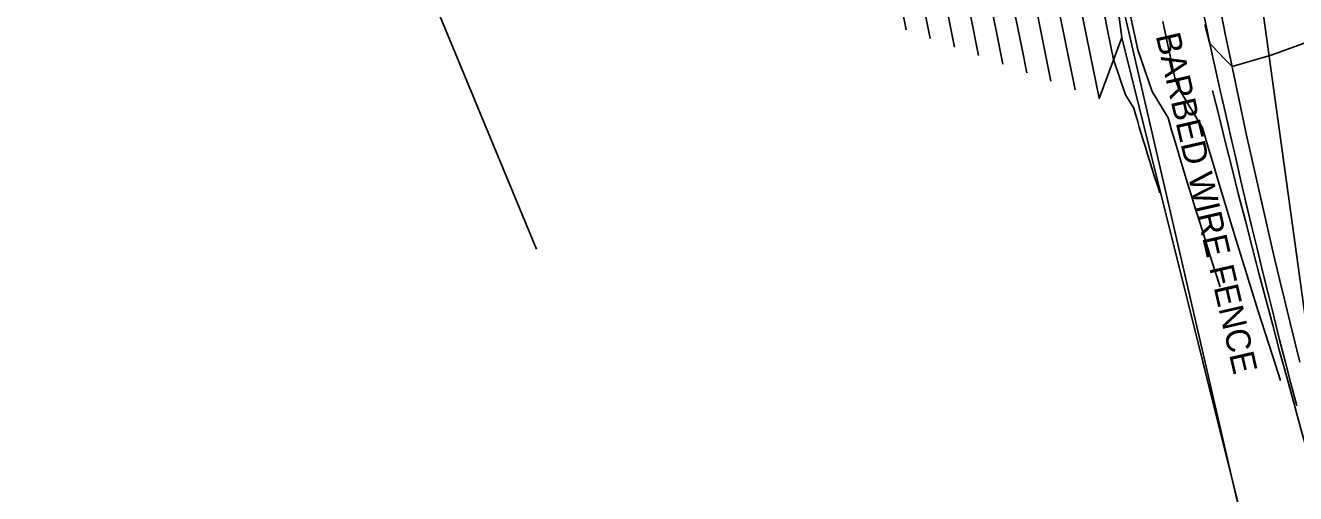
# Model space of a CAD drawing. Extents: x 487096 to 489566, y 221939 to 224454.
# Drawn here: x 488250.6 to 488416.7, y 222799.6 to 222860.8 of the extents above; entities that cross this region are included whole.
import ezdxf

# ---------------------------------------------------------------- set-up
doc = ezdxf.new("R2010")
doc.units = 0
for name, color, linetype in [('SV_FENC_FENCES', 7, 'Continuous'), ('SV_FENC_FENCES_TX', 7, 'Continuous'), ('SV_GDRL_GR', 7, 'Continuous'), ('SV_ROAD_BITRD', 7, 'Continuous'), ('SV_ROWL_HWYLOC', 7, 'Continuous'), ('SV_SURF_INDEX_CONTOUR', 7, 'Continuous'), ('SV_SURF_INTER_CONTOUR', 7, 'Continuous'), ('SV_TRAF_PVMTL', 7, 'Continuous'), ('SV_TREE_TREEVEG', 7, 'Continuous'), ('SV_UTOH_OVERHEAD_LINES', 7, 'Continuous'), ('SV_WATR_INWETF', 7, 'Continuous')]:
    doc.layers.add(name, color=color, linetype=linetype)

msp = doc.modelspace()

# ---------------------------------------------------------------- linework, layer by layer
at = {"layer": 'SV_FENC_FENCES'}
msp.add_lwpolyline([(488391.05, 222851.3), (488394, 222859.24), (488391.81, 222875.89)], dxfattribs=at)
at = {"layer": 'SV_GDRL_GR'}
msp.add_lwpolyline([(488405.88, 222852.34), (488406.72, 222848.92), (488407.57, 222845.5), (488408.43, 222842.09), (488409.29, 222838.67), (488410.17, 222835.26), (488411.05, 222831.85), (488411.94, 222828.45), (488412.83, 222825.04), (488413.74, 222821.64), (488414.65, 222818.24), (488415.57, 222814.84), (488416.5, 222811.45), (488417.43, 222808.05), (488418.37, 222804.66), (488419.33, 222801.27), (488420.28, 222797.88)], dxfattribs=at)
at = {"layer": 'SV_ROAD_BITRD'}
msp.add_lwpolyline([(488403.06, 222870.14), (488403.68, 222867.17), (488404.3, 222864.2), (488404.94, 222861.24), (488405.58, 222858.27), (488406.23, 222855.31), (488406.88, 222852.34), (488407.55, 222849.38), (488408.22, 222846.42), (488408.9, 222843.47), (488409.59, 222840.51), (488410.28, 222837.56), (488410.98, 222834.61), (488411.69, 222831.66), (488412.41, 222828.71), (488413.14, 222825.76), (488413.87, 222822.82), (488414.61, 222819.88), (488415.36, 222816.93), (488416.12, 222814), (488416.89, 222811.06)], dxfattribs=at)
at = {"layer": 'SV_ROWL_HWYLOC'}
msp.add_lwpolyline([(488415.39, 223241.14), (488415.01, 223209.78), (488407.48, 223152.68), (488402.8, 223123.48), (488396.48, 223078.48), (488389.41, 223042.33), (488386.96, 223020.94), (488384.51, 222999.56), (488386.77, 222964.1), (488387.65, 222918.23), (488391.82, 222875.91), (488394, 222859.24), (488415.21, 222774.39)], dxfattribs=at)
at = {"layer": 'SV_SURF_INDEX_CONTOUR'}
for points in [[(488361.03, 222885.62), (488362.59, 222876.48), (488363.45, 222872.07), (488364.06, 222869.06), (488365.81, 222860.25)], [(488376.78, 222879.28), (488377.31, 222876.19), (488379.42, 222865.36), (488380.93, 222857.95), (488381.59, 222854.65)], [(488406.87, 222826.66), (488406.19, 222828.78), (488405.53, 222830.83), (488404.9, 222832.83), (488404.28, 222834.78), (488403.69, 222836.68), (488403.12, 222838.53), (488402.56, 222840.34), (488402.03, 222842.1), (488401.51, 222843.82), (488401.01, 222845.5), (488400.52, 222847.14), (488400.05, 222848.74), (488397.96, 222852.18), (488396.11, 222857.64), (488395.64, 222859.89), (488393.92, 222867.71)]]:
    msp.add_lwpolyline(points, dxfattribs=at)
at = {"layer": 'SV_SURF_INTER_CONTOUR'}
for points in [[(488330.36, 223253.85), (488333.72, 223206.86), (488336.41, 223199.13), (488339.34, 223176.14), (488341.3, 223168.89), (488341.3, 223168.78), (488341.3, 223168.7), (488341.25, 223167.91), (488342.11, 223162.38), (488351.69, 223120.88), (488344.09, 223092.29), (488344.07, 223086.72), (488348.88, 223046.65), (488349.88, 223039.17), (488349.71, 223006.96), (488350.12, 222991.02), (488358.36, 222946.07), (488360.64, 222921.92), (488363.3, 222889.49), (488365.53, 222876.42), (488366.64, 222870.73), (488367.44, 222866.83), (488368.96, 222859.13)], [(488372.12, 222858.01), (488370.81, 222864.61), (488369.84, 222869.39), (488368.47, 222876.36), (488365.75, 222892.37), (488363.35, 222921.55), (488360.89, 222947.67), (488353.37, 222988.63), (488352.92, 223006.27), (488353.11, 223041.95), (488352.7, 223045.03), (488348.94, 223076.26), (488347.53, 223089.21), (488348.29, 223091.81), (488355.92, 223120.53), (488348.77, 223151.52), (488346.42, 223166.72), (488346.54, 223168.9), (488346.55, 223169.1), (488346.56, 223169.4), (488341.16, 223189.35), (488339.56, 223201.89), (488338.09, 223206.12), (488336.26, 223231.76)], [(488384.74, 222853.53), (488384.31, 222855.73), (488382.62, 222864.02), (488380.25, 222876.13), (488375.52, 222903.91), (488374.19, 222920.07), (488370.98, 222954.08), (488366.4, 222979.07), (488365.77, 223003.54)], [(488368.99, 223002.86), (488369.65, 222976.67), (488373.5, 222955.68), (488376.9, 222919.7), (488377.96, 222906.79), (488383.2, 222876.07), (488385.81, 222862.68), (488387.68, 222853.51), (488387.9, 222852.41)], [(488372.2, 223002.18), (488372.91, 222974.28), (488376.03, 222957.28), (488379.61, 222919.33), (488380.4, 222909.68), (488386.14, 222876.01), (488389.01, 222861.34), (488391.05, 222851.32), (488391.06, 222851.3), (488391.06, 222851.29), (488391.07, 222851.27), (488391.07, 222851.26)], [(488375.41, 223001.5), (488376.16, 222971.89), (488378.55, 222958.88), (488382.32, 222918.96), (488382.84, 222912.56), (488389.09, 222875.95), (488392.2, 222859.99), (488392.94, 222856.38), (488394.51, 222851.74), (488395.56, 222850.02), (488395.79, 222849.22), (488396.04, 222848.4), (488396.29, 222847.55), (488396.55, 222846.69), (488396.82, 222845.81), (488397.09, 222844.91), (488397.38, 222843.98), (488397.68, 222843.03), (488397.98, 222842.05), (488398.3, 222841.05), (488398.63, 222840.02), (488398.97, 222838.96)], [(488375.28, 222856.89), (488374.19, 222862.39), (488373.03, 222868.05), (488371.42, 222876.31), (488368.19, 222895.26), (488366.06, 222921.18), (488363.41, 222949.28), (488356.63, 222986.24)], [(488359.88, 222983.85), (488365.93, 222950.88), (488368.77, 222920.81), (488370.63, 222898.14), (488374.36, 222876.25), (488376.23, 222866.71), (488377.56, 222860.17), (488378.43, 222855.77)], [(488399.39, 222861.37), (488400.95, 222853.99), (488401.42, 222852.62), (488404.55, 222847.46), (488405.26, 222845.06), (488405.98, 222842.61), (488406.73, 222840.09), (488407.51, 222837.51), (488408.31, 222834.87), (488409.15, 222832.16), (488410, 222829.39), (488410.89, 222826.54), (488411.81, 222823.61), (488412.76, 222820.61), (488413.74, 222817.53), (488414.76, 222814.37)], [(488404.86, 222860.98), (488405.54, 222858.43), (488405.65, 222858.33), (488405.81, 222858.16), (488407.46, 222856.48), (488408.42, 222855.45), (488413.56, 222856.97), (488419.08, 222858.97)]]:
    msp.add_lwpolyline(points, dxfattribs=at)
at = {"layer": 'SV_TRAF_PVMTL'}
msp.add_lwpolyline([(488405.4, 222870.58), (488405.92, 222867.87), (488406.45, 222865.17), (488406.99, 222862.46), (488407.53, 222859.76), (488408.08, 222857.06), (488408.64, 222854.37), (488409.21, 222851.67), (488409.79, 222848.97), (488410.37, 222846.28), (488410.96, 222843.59), (488411.56, 222840.9), (488412.17, 222838.21), (488412.78, 222835.53), (488413.41, 222832.84), (488414.04, 222830.16), (488414.68, 222827.48), (488415.32, 222824.8), (488415.98, 222822.12), (488416.64, 222819.45), (488417.31, 222816.77)], dxfattribs=at)
at = {"layer": 'SV_TREE_TREEVEG'}
msp.add_lwpolyline([(488469.57, 222626.73), (488414.36, 222775.8), (488391.31, 222875.65), (488384.76, 223013.78), (488396.28, 223079.01), (488413.65, 223210.14), (488414.48, 223247.55), (488427.96, 223341.62), (488424.88, 223443.61), (488411.44, 223499.76), (488395.39, 223528.76), (488373.34, 223524.5)], dxfattribs=at)
at = {"layer": 'SV_UTOH_OVERHEAD_LINES'}
msp.add_lwpolyline([(488477.01, 222631.44), (488424.13, 222778.25), (488391.68, 223012.96), (488449.87, 223205.72), (488470, 223438.33), (488349.56, 223622.89), (488159.18, 223693.12), (487993.17, 223755.78), (487804.2, 223830.22), (487742.26, 223860.21)], dxfattribs=at)
at = {"layer": 'SV_WATR_INWETF'}
msp.add_lwpolyline([(488317.45, 222831.55), (488289.87, 222898.26), (488291.06, 222931.37), (488290.46, 222991.69), (488252.55, 223050.25)], dxfattribs=at)

# ---------------------------------------------------------------- texts
at = {"layer": 'SV_FENC_FENCES_TX'}
msp.add_text('BARBED WIRE FENCE', height=3.2, rotation=282.9706, dxfattribs=at).set_placement((488398.43, 222859.5))

doc.saveas('drawing.dxf')
